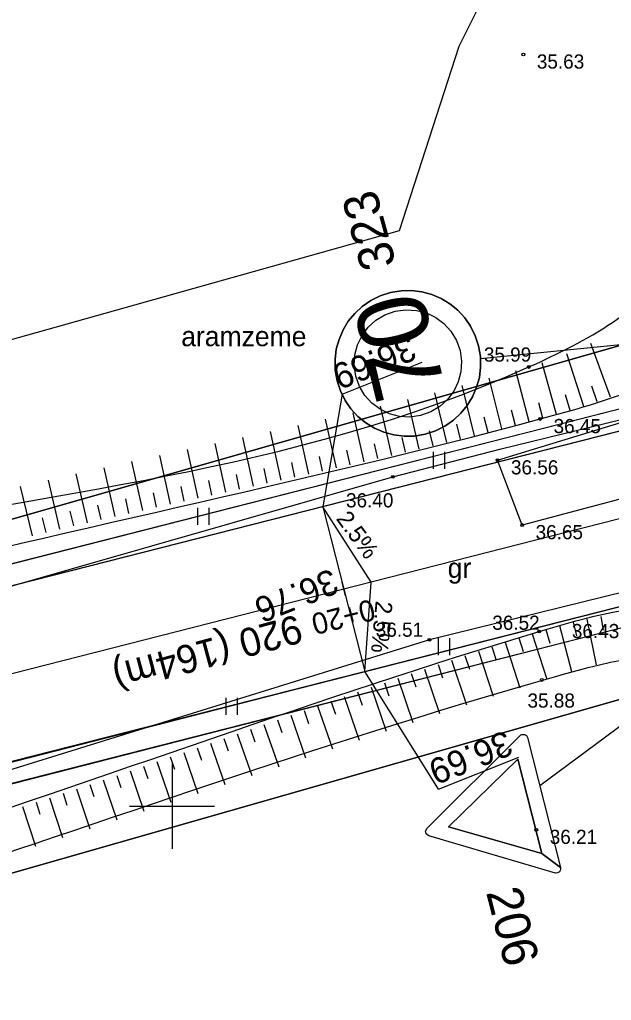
# Model space of a CAD drawing. Extents: x 469981 to 472086, y 246785 to 247785.
# Drawn here: x 471944.62 to 471965.51, y 247643.15 to 247677.75 of the extents above; entities that cross this region are included whole.
import ezdxf

# ---------------------------------------------------------------- set-up
doc = ezdxf.new("R2010")
doc.units = 0
for name, color, linetype in [('0_920', 7, 'Continuous'), ('0_Asfalta_mala', 7, 'Continuous'), ('0_Asfalta_Nomale', 7, 'Continuous'), ('0_Horiz_aprakst', 7, 'Continuous'), ('0_Ruut_Braukt', 7, 'Continuous'), ('0_Ruut_nomale', 7, 'Continuous'), ('0_vertikals', 7, 'Continuous'), ('0_vertkals_cipari', 7, 'Continuous'), ('0_Ziimes', 7, 'Continuous'), ('21', 7, 'Continuous'), ('6_piketaza', 7, 'Continuous'), ('CELI_CMAL_####_####_#', 7, 'Continuous'), ('CELI_CSEG_####_TKST_#', 7, 'Continuous'), ('CELI_SEGL_####_####_#', 7, 'Continuous'), ('GEOD_ELEM_####_####_#', 7, 'Continuous'), ('RAMI_UZMR_####_####_#', 7, 'Continuous'), ('RELJ_AATZ_####_TKST_#', 7, 'Continuous'), ('RELJ_ELEM_####_####_#', 7, 'Continuous'), ('RELJ_NOGA_####_####_#', 7, 'Continuous'), ('RELJ_NOGL_####_####_#', 7, 'Continuous'), ('ROBZ_IERR_####_####_#', 7, 'Continuous'), ('ROBZ_PROJ_####_####_#', 7, 'Continuous'), ('TERT_ELEM_####_####_#', 7, 'Continuous'), ('TERT_IZMT_####_TKST_#', 7, 'Continuous')]:
    doc.layers.add(name, color=color, linetype=linetype)

msp = doc.modelspace()

# ---------------------------------------------------------------- linework, layer by layer
at = {"layer": '0_920'}
msp.add_line((471966.623, 247660.345), (471937.512, 247652.939), dxfattribs=at)
at = {"layer": '0_Asfalta_mala'}
for p, q in [((471969.808, 247664.25), (471936.725, 247655.835)), ((471967.128, 247657.377), (471938.299, 247650.044))]:
    msp.add_line(p, q, dxfattribs=at)
at = {"layer": '0_Asfalta_Nomale'}
for p, q in [((471969.623, 247664.977), (471936.528, 247656.558)), ((471967.313, 247656.651), (471938.496, 247649.32))]:
    msp.add_line(p, q, dxfattribs=at)
at = {"layer": '0_Ruut_Braukt'}
for p, q in [((471969.808, 247664.25), (471936.725, 247655.835)), ((471938.299, 247650.044), (471967.128, 247657.377))]:
    msp.add_line(p, q, dxfattribs=at)
at = {"layer": '0_Ruut_nomale'}
msp.add_lwpolyline([(471975.078, 247671.288), (471975.01, 247670.031), (471974.714, 247668.795), (471974.079, 247667.423), (471973.236, 247666.298), (471972.029, 247665.253), (471970.485, 247664.46), (471969.612, 247664.2), (471936.725, 247655.835), (471873.301, 247637.47), (471870.881, 247637.615), (471936.528, 247656.558), (471969.993, 247665.083), (471970.891, 247665.451), (471971.391, 247665.732), (471971.641, 247665.897), (471972.134, 247666.276), (471972.814, 247666.952), (471973.343, 247667.66), (471973.808, 247668.529), (471974.107, 247669.372), (471974.313, 247670.554), (471974.328, 247671.26)], close=True, dxfattribs=at)
for points in [[(471937.525, 247649.81), (471953.772, 247653.98), (471966.643, 247657.254)], [(471966.674, 247656.488), (471937.664, 247649.079)]]:
    msp.add_lwpolyline(points, dxfattribs=at)
at = {"layer": '0_vertikals'}
for p, q in [((471956.01, 247664.535), (471958.837, 247665.669)), ((471956.01, 247664.535), (471955.326, 247660.566)), ((471959.413, 247650.597), (471956.806, 247654.752)), ((471959.413, 247650.597), (471962.241, 247651.732))]:
    msp.add_line(p, q, dxfattribs=at)
msp.add_lwpolyline([(471956.806, 247654.752), (471957.035, 247657.906), (471955.326, 247660.566)], close=True, dxfattribs=at)
at = {"layer": '0_Ziimes'}
for p, q in [((471966.493, 247666.346), (471960.891, 247665.778)), ((471968.015, 247654.44), (471962.984, 247650.724))]:
    msp.add_line(p, q, dxfattribs=at)
for points in [[(471957.351, 247668.006), (471957.019, 247667.84), (471956.718, 247667.632), (471956.453, 247667.386), (471956.225, 247667.107), (471956.039, 247666.8), (471955.896, 247666.469), (471955.801, 247666.12), (471955.755, 247665.757), (471955.763, 247665.386), (471955.826, 247665.011), (471955.943, 247664.649), (471956.108, 247664.316), (471956.316, 247664.015), (471956.562, 247663.75), (471956.841, 247663.522), (471957.149, 247663.336), (471957.479, 247663.194), (471957.829, 247663.098), (471958.191, 247663.053), (471958.563, 247663.06), (471958.938, 247663.123), (471959.3, 247663.24), (471959.633, 247663.406), (471959.933, 247663.614), (471960.199, 247663.86), (471960.426, 247664.139), (471960.613, 247664.446), (471960.755, 247664.777), (471960.851, 247665.126), (471960.896, 247665.489), (471960.889, 247665.86), (471960.826, 247666.235), (471960.708, 247666.597), (471960.543, 247666.93), (471960.335, 247667.231), (471960.089, 247667.496), (471959.81, 247667.724), (471959.503, 247667.91), (471959.172, 247668.052), (471958.823, 247668.148), (471958.46, 247668.193), (471958.089, 247668.186), (471957.713, 247668.123), (471957.351, 247668.006)], [(471955.826, 247665.011), (471955.763, 247665.386), (471955.755, 247665.757), (471955.801, 247666.12), (471955.896, 247666.469), (471956.039, 247666.8), (471956.225, 247667.107), (471956.453, 247667.386), (471956.718, 247667.632), (471957.019, 247667.84), (471957.351, 247668.006), (471957.713, 247668.123), (471958.089, 247668.186), (471958.46, 247668.193), (471958.823, 247668.148), (471959.172, 247668.052), (471959.503, 247667.91), (471959.81, 247667.724), (471960.089, 247667.496), (471960.335, 247667.231), (471960.543, 247666.93), (471960.708, 247666.597), (471960.826, 247666.235), (471960.826, 247666.235), (471960.889, 247665.86), (471960.896, 247665.489), (471960.851, 247665.126), (471960.755, 247664.777), (471960.613, 247664.446), (471960.426, 247664.139), (471960.199, 247663.86), (471959.933, 247663.614), (471959.633, 247663.406), (471959.3, 247663.24), (471958.938, 247663.123), (471958.563, 247663.06), (471958.191, 247663.053), (471957.829, 247663.098), (471957.479, 247663.194), (471957.149, 247663.336), (471956.841, 247663.522), (471956.562, 247663.75), (471956.316, 247664.015), (471956.108, 247664.316), (471955.943, 247664.649), (471955.826, 247665.011)], [(471957.199, 247667.142), (471957.517, 247667.334), (471957.878, 247667.462), (471958.257, 247667.515), (471958.629, 247667.492), (471958.983, 247667.399), (471959.31, 247667.241), (471959.602, 247667.024), (471959.849, 247666.753), (471960.041, 247666.434), (471960.169, 247666.073), (471960.222, 247665.694), (471960.199, 247665.323), (471960.105, 247664.969), (471959.947, 247664.641), (471959.73, 247664.349), (471959.459, 247664.103), (471959.14, 247663.911), (471958.779, 247663.783), (471958.4, 247663.73), (471958.029, 247663.753), (471957.675, 247663.846), (471957.347, 247664.004), (471957.056, 247664.222), (471956.809, 247664.493), (471956.617, 247664.811), (471956.489, 247665.172), (471956.436, 247665.551), (471956.459, 247665.922), (471956.552, 247666.277), (471956.711, 247666.604), (471956.928, 247666.896), (471957.199, 247667.142)], [(471956.489, 247665.172), (471956.436, 247665.551), (471956.459, 247665.922), (471956.552, 247666.277), (471956.711, 247666.604), (471956.928, 247666.896), (471957.199, 247667.142), (471957.517, 247667.334), (471957.878, 247667.462), (471958.257, 247667.515), (471958.629, 247667.492), (471958.983, 247667.399), (471959.31, 247667.241), (471959.602, 247667.024), (471959.849, 247666.753), (471960.041, 247666.434), (471960.169, 247666.073), (471960.222, 247665.694), (471960.199, 247665.323), (471960.105, 247664.969), (471959.947, 247664.641), (471959.73, 247664.349), (471959.459, 247664.103), (471959.14, 247663.911), (471958.779, 247663.783), (471958.4, 247663.73), (471958.029, 247663.753), (471957.675, 247663.846), (471957.347, 247664.004), (471957.056, 247664.222), (471956.809, 247664.493), (471956.617, 247664.811), (471956.489, 247665.172)], [(471962.207, 247651.662), (471963.053, 247648.337), (471959.765, 247649.271), (471962.207, 247651.662)]]:
    msp.add_lwpolyline(points, dxfattribs=at)
for points in [[(471957.675, 247663.846), (471957.347, 247664.004), (471957.056, 247664.222), (471956.809, 247664.493), (471956.617, 247664.811), (471956.489, 247665.172), (471956.436, 247665.551), (471956.459, 247665.922), (471956.552, 247666.277), (471956.711, 247666.604), (471956.928, 247666.896), (471957.199, 247667.142), (471957.517, 247667.334), (471957.878, 247667.462), (471958.257, 247667.515), (471958.629, 247667.492), (471958.983, 247667.399), (471959.31, 247667.241), (471959.602, 247667.024), (471959.849, 247666.753), (471960.041, 247666.434), (471960.169, 247666.073), (471960.222, 247665.694), (471960.199, 247665.323), (471960.105, 247664.969), (471959.947, 247664.641), (471959.73, 247664.349), (471959.459, 247664.103), (471959.14, 247663.911), (471958.779, 247663.783), (471958.4, 247663.73), (471958.029, 247663.753)], [(471963.677, 247647.686), (471963.606, 247647.646), (471963.543, 247647.643), (471959.068, 247648.958), (471958.977, 247649.024), (471958.955, 247649.125), (471959.009, 247649.222), (471962.286, 247652.489), (471962.319, 247652.516), (471962.347, 247652.529), (471962.362, 247652.535), (471962.444, 247652.534), (471962.511, 247652.493), (471962.551, 247652.423), (471963.718, 247647.836), (471963.053, 247648.338), (471962.207, 247651.663), (471959.765, 247649.271), (471963.053, 247648.338), (471963.718, 247647.836), (471963.717, 247647.754)], [(471959.765, 247649.271), (471962.207, 247651.662), (471963.053, 247648.337)]]:
    msp.add_lwpolyline(points, close=True, dxfattribs=at)
at = {"layer": '21'}
msp.add_line((471975.449, 247662.59), (471937.512, 247652.939), dxfattribs=at)
at = {"layer": '6_piketaza'}
msp.add_lwpolyline([(471956.128, 247657.417), (471956.004, 247657.901)], dxfattribs=at)
at = {"layer": 'CELI_CMAL_####_####_#'}
for points in [[(471875.663, 247637.516), (471893.917, 247642.844), (471914.511, 247649.081), (471937.843, 247655.917), (471957.797, 247661.618), (471961.625, 247662.609), (471967.542, 247664.048)], [(471975.069, 247653.452), (471973.432, 247655.323), (471971.819, 247656.723), (471969.738, 247657.563), (471967.595, 247657.966), (471959.086, 247655.87), (471939.59, 247649.827), (471915.758, 247643.551), (471894.011, 247637.496), (471877.558, 247632.705), (471871.967, 247630.721)]]:
    msp.add_lwpolyline(points, dxfattribs=at)
at = {"layer": 'CELI_SEGL_####_####_#'}
msp.add_lwpolyline([(471975.87, 247652.699), (471974.792, 247655.969), (471969.93, 247658.517), (471968.166, 247661.457), (471962.364, 247659.919), (471961.494, 247662.205), (471967.542, 247664.048)], dxfattribs=at)
at = {"layer": 'GEOD_ELEM_####_####_#'}
for p, q in [((471950, 247651.5), (471950, 247650)), ((471948.5, 247650), (471950, 247650)), ((471950, 247650), (471950, 247648.5)), ((471950, 247650), (471951.5, 247650))]:
    msp.add_line(p, q, dxfattribs=at)
at = {"layer": 'RAMI_UZMR_####_####_#'}
msp.add_lwpolyline([(471806.563, 247631.532), (471842.307, 247641.196), (471851.789, 247644.535), (471859.866, 247647.874), (471866.363, 247650.158), (471872.333, 247648.928), (471913.773, 247657.89), (471958.034, 247670.311), (471960.141, 247676.812), (471962.599, 247681.733), (471965.233, 247685.774), (471985.777, 247687.531)], dxfattribs=at)
at = {"layer": 'RELJ_ELEM_####_####_#'}
for centre in [(471962.407, 247676.52), (471962.601, 247665.495), (471962.999, 247663.66), (471961.494, 247662.205), (471957.797, 247661.618), (471962.364, 247659.919), (471962.961, 247656.163), (471959.086, 247655.87), (471963.055, 247654.454), (471962.863, 247649.17)]:
    msp.add_circle(centre, 0.05, dxfattribs=at)
at = {"layer": 'RELJ_NOGA_####_####_#'}
for p, q in [((471965.483, 247664.43), (471964.782, 247666.328)), ((471964.538, 247664.104), (471963.944, 247665.954)), ((471962.614, 247663.559), (471962.144, 247665.362)), ((471963.579, 247663.818), (471963.071, 247665.64)), ((471961.645, 247663.309), (471961.194, 247665.095)), ((471960.675, 247663.067), (471960.239, 247664.836)), ((471965.012, 247664.261), (471964.819, 247664.823)), ((471958.73, 247662.6), (471958.322, 247664.344)), ((471959.703, 247662.831), (471959.283, 247664.586)), ((471964.06, 247663.957), (471963.896, 247664.507)), ((471957.756, 247662.374), (471957.358, 247664.108)), ((471963.097, 247663.686), (471962.952, 247664.23)), ((471955.805, 247661.933), (471955.423, 247663.655)), ((471956.781, 247662.152), (471956.392, 247663.879)), ((471961.16, 247663.187), (471961.027, 247663.72)), ((471962.13, 247663.433), (471961.991, 247663.971)), ((471954.829, 247661.717), (471954.451, 247663.435)), ((471960.19, 247662.948), (471960.062, 247663.477)), ((471952.875, 247661.291), (471952.502, 247663.004)), ((471953.852, 247661.503), (471953.479, 247663.218)), ((471958.244, 247662.486), (471958.123, 247663.008)), ((471959.217, 247662.715), (471959.093, 247663.239)), ((471951.898, 247661.078), (471951.525, 247662.792)), ((471957.269, 247662.262), (471957.15, 247662.781)), ((471949.944, 247660.652), (471949.567, 247662.369)), ((471950.921, 247660.866), (471950.547, 247662.58)), ((471955.317, 247661.825), (471955.203, 247662.341)), ((471956.293, 247662.042), (471956.178, 247662.559)), ((471947.991, 247660.219), (471947.604, 247661.941)), ((471948.967, 247660.437), (471948.586, 247662.156)), ((471953.364, 247661.397), (471953.252, 247661.911)), ((471954.341, 247661.61), (471954.228, 247662.125)), ((471947.016, 247659.998), (471946.621, 247661.724)), ((471952.387, 247661.184), (471952.275, 247661.698)), ((471945.068, 247659.544), (471944.654, 247661.276)), ((471946.042, 247659.773), (471945.638, 247661.502)), ((471950.432, 247660.759), (471950.32, 247661.274)), ((471951.409, 247660.972), (471951.298, 247661.486)), ((471949.456, 247660.545), (471949.342, 247661.06)), ((471947.504, 247660.109), (471947.386, 247660.626)), ((471948.479, 247660.328), (471948.364, 247660.844)), ((471945.555, 247659.659), (471945.432, 247660.178)), ((471946.529, 247659.886), (471946.409, 247660.404)), ((471963.678, 247656.37), (471964.11, 247654.753)), ((471964.164, 247656.491), (471964.276, 247656.006)), ((471964.652, 247656.598), (471964.981, 247654.988)), ((471965.143, 247656.693), (471965.228, 247656.211)), ((471962.72, 247656.087), (471963.229, 247654.48)), ((471963.197, 247656.235), (471963.342, 247655.752)), ((471961.767, 247655.782), (471962.286, 247654.181)), ((471962.243, 247655.935), (471962.397, 247655.454)), ((471960.816, 247655.472), (471961.341, 247653.878)), ((471961.292, 247655.627), (471961.448, 247655.148)), ((471959.393, 247655), (471959.552, 247654.526)), ((471959.867, 247655.158), (471960.394, 247653.573)), ((471960.342, 247655.316), (471960.499, 247654.839)), ((471958.445, 247654.68), (471958.604, 247654.209)), ((471958.919, 247654.84), (471959.448, 247653.266)), ((471957.499, 247654.357), (471957.659, 247653.891)), ((471957.972, 247654.519), (471958.504, 247652.957)), ((471956.553, 247654.033), (471956.712, 247653.57)), ((471957.026, 247654.195), (471957.557, 247652.646)), ((471955.608, 247653.706), (471955.767, 247653.248)), ((471956.08, 247653.869), (471956.611, 247652.335)), ((471954.663, 247653.378), (471954.821, 247652.924)), ((471955.136, 247653.542), (471955.663, 247652.022)), ((471953.719, 247653.049), (471953.875, 247652.6)), ((471954.191, 247653.213), (471954.715, 247651.708)), ((471952.775, 247652.72), (471952.929, 247652.275)), ((471953.247, 247652.884), (471953.766, 247651.394)), ((471951.358, 247652.227), (471951.866, 247650.766)), ((471951.83, 247652.391), (471951.983, 247651.951)), ((471952.302, 247652.555), (471952.816, 247651.08)), ((471950.413, 247651.9), (471950.912, 247650.452)), ((471950.885, 247652.063), (471951.037, 247651.627)), ((471949.467, 247651.574), (471949.96, 247650.139)), ((471949.94, 247651.737), (471950.089, 247651.304)), ((471948.521, 247651.251), (471949.006, 247649.827)), ((471948.994, 247651.412), (471949.141, 247650.983)), ((471947.574, 247650.93), (471948.051, 247649.515)), ((471948.048, 247651.09), (471948.192, 247650.664)), ((471946.625, 247650.613), (471947.093, 247649.206)), ((471947.1, 247650.772), (471947.241, 247650.348)), ((471945.2, 247650.145), (471945.337, 247649.725)), ((471945.676, 247650.3), (471946.134, 247648.898)), ((471946.151, 247650.456), (471946.29, 247650.035)), ((471944.724, 247649.992), (471945.174, 247648.592))]:
    msp.add_line(p, q, dxfattribs=at)
for points in [[(471870.274, 247637.593), (471875.049, 247639.08), (471894.013, 247643.622), (471914.128, 247650.189), (471937.616, 247657.537), (471962.999, 247663.66), (471969.383, 247666.572), (471971.553, 247670.335), (471971.102, 247675.998), (471970.392, 247686.477)], [(471872.369, 247630.301), (471877.035, 247631.779), (471891.063, 247635.461), (471916.26, 247641.941), (471939.936, 247648.535), (471962.961, 247656.163), (471968.243, 247657.04), (471972.035, 247655.629), (471974.189, 247651.025), (471974.236, 247640.547), (471974.113, 247637.831)]]:
    msp.add_spline(points, degree=3, dxfattribs=at)
at = {"layer": 'RELJ_NOGL_####_####_#'}
for points in [[(471869.749, 247640.405), (471874.381, 247641.599), (471893.987, 247646.203), (471913.506, 247651.854), (471937.092, 247659.264), (471962.601, 247665.495), (471967.69, 247669.208), (471968.009, 247677.365), (471967.21, 247685.336), (471967.187, 247686.78)], [(471873.775, 247627.995), (471877.996, 247629.001), (471893.546, 247633.06), (471916.609, 247640.032), (471940.388, 247647.116), (471963.51, 247654.569), (471969.26, 247654.727), (471970.873, 247652.327), (471971.171, 247640.235), (471971.159, 247637.819)]]:
    msp.add_spline(points, degree=3, dxfattribs=at)
at = {"layer": 'ROBZ_IERR_####_####_#'}
for points in [[(471968.673, 247704.844), (471968.166, 247666.92), (471863.461, 247637.05), (471850.386, 247675.013)], [(471879.163, 247574.024), (471880.66, 247583.5), (471867.531, 247625.725), (471968.24, 247654.462), (471970.607, 247591.56)]]:
    msp.add_lwpolyline(points, dxfattribs=at)
at = {"layer": 'ROBZ_PROJ_####_####_#'}
msp.add_lwpolyline([(471863.461, 247637.05), (471968.166, 247666.92), (471968.24, 247654.462), (471867.531, 247625.725)], close=True, dxfattribs=at)
msp.add_lwpolyline([(471863.461, 247637.05), (471968.166, 247666.92), (471968.24, 247654.462), (471867.531, 247625.725)], close=True, dxfattribs=at)
at = {"layer": 'TERT_ELEM_####_####_#'}
for p, q in [((471959.227, 247661.9), (471959.227, 247662.5)), ((471959.627, 247661.9), (471959.627, 247662.5)), ((471950.915, 247659.928), (471950.915, 247660.528)), ((471951.315, 247659.928), (471951.315, 247660.528)), ((471959.408, 247655.326), (471959.408, 247655.926)), ((471959.808, 247655.326), (471959.808, 247655.926)), ((471951.916, 247653.219), (471951.916, 247653.819)), ((471952.316, 247653.219), (471952.316, 247653.819))]:
    msp.add_line(p, q, dxfattribs=at)

# ---------------------------------------------------------------- texts
at = {"layer": '0_Horiz_aprakst'}
msp.add_text('920 (164m)', height=1, rotation=195.1225, dxfattribs=at).set_placement((471954.429, 247656.771))
at = {"layer": '0_vertkals_cipari'}
for s, height, rotation, p in [('36.69', 0.9, 201.859, (471958.375, 247666.633)), ('2.5%', 0.5993, 306.334, (471955.771, 247660.138)), ('36.76', 0.9, 201.859, (471955.629, 247658.402)), ('2.5%', 0.5993, 264.6893, (471957.194, 247657.257)), ('36.69', 0.9, 201.859, (471961.779, 247652.695))]:
    msp.add_text(s, height=height, rotation=rotation, dxfattribs=at).set_placement(p)
at = {"layer": '0_Ziimes'}
for s, height, rotation, p in [('323', 1.25, 105.3439, (471957.922, 247669.12)), ('70', 2.4807, 103.7617, (471959.669, 247664.695)), ('206', 1.25, 284.2722, (471961.084, 247646.971))]:
    msp.add_text(s, height=height, rotation=rotation, dxfattribs=at).set_placement(p)
at = {"layer": '6_piketaza'}
msp.add_text('0+20', height=0.75, rotation=194.2722, dxfattribs=at).set_placement((471957.055, 247657.317))
at = {"layer": 'CELI_CSEG_####_TKST_#'}
msp.add_text('gr', height=0.7, dxfattribs=at).set_placement((471959.734, 247658.056))
at = {"layer": 'RELJ_AATZ_####_TKST_#'}
for s, p in [('35.63', (471962.881, 247676.02)), ('35.99', (471961.011, 247665.683)), ('36.45', (471963.472, 247663.16)), ('36.56', (471961.967, 247661.705)), ('36.40', (471956.143, 247660.542)), ('36.65', (471962.837, 247659.419)), ('36.52', (471961.307, 247656.223)), ('36.51', (471957.193, 247655.978)), ('36.43', (471964.119, 247655.93)), ('35.88', (471962.551, 247653.478)), ('36.21', (471963.336, 247648.67))]:
    msp.add_text(s, height=0.5, dxfattribs=at).set_placement(p)
at = {"layer": 'TERT_IZMT_####_TKST_#'}
msp.add_text('aramzeme', height=0.7, dxfattribs=at).set_placement((471950.325, 247666.227))

doc.saveas('drawing.dxf')
